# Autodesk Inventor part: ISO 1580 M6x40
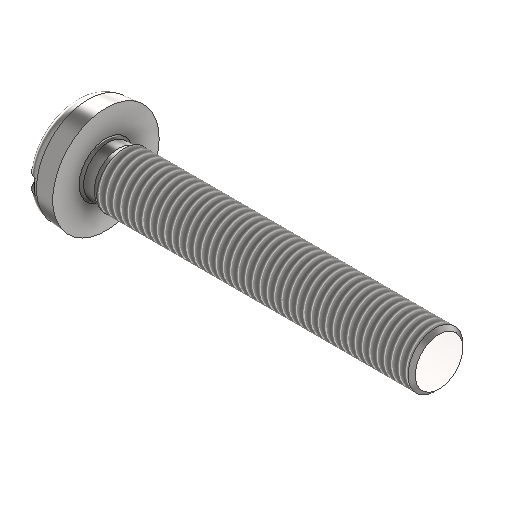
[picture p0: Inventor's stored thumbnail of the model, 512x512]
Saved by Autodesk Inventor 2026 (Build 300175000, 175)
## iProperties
Created: 2015-09
Part Number: ISO 1580 M6x40
Material: Steel, Mild
Document SubType Name: Modeling
Designer: Lars Bertram Pedersen
Mass: 10.5111 g
Surface Area: 10.1633 cm^2
Volume: 1.33899 cm^3
Density: 7.85 g/cm^3
Appearance: Semi-Polished
Description: Slotted pan head screws
Stock Number: Lager
Author: Lars Bertram Pedersen
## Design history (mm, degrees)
sketch "Sketch1"
  geometry: L1 (-3.6, 0)-(36.4, 0); L2 (36.4, 0)-(36.4, 3); L3 (36.4, 3)-(2, 3); L4 (2, 3)-(1.389, 2.689); L5 (1.389, 2.689)-(0, 2.689); L6 (0, 2.689)-(0, 5.815); L7 (-3.6, 0)-(-3.6, 5.5); L8 (0, 5.815)-(-3.6, 5.5); 1 further point
  constraints: 16 end point, 3 parallel, 1 horizontal, 1 perpendicular
  dimensions: "d18" = 36.4 distance between parallel lines of L2 L6; "d19" = 6 diameter of L3 L1; "d20" = 85 deg angle of L7 L8; "d21" = 153 deg angle of L5 L4; "d22" = 5.37716 diameter of L5 L1; "d23" = 11 diameter of L7.end L1
revolve "Revolution1" sketch "Sketch1" stored, may be unused: angle "d24" = 90 deg
chamfer "Chamfer1" distance "d25" = 0.4; stored, may be unused: second distance "d26" = 2, angle "d27" = 45 deg
thread "Thread1" dims "d28" = 10, "d29" = 0
fillet "Fillet1" dims "d34" = 1.8
sketch "Sketch2"
  geometry: L1 (0.8, -7.5)-(-0.8, -7.5); L2 (-0.8, -7.5)-(-0.8, 7.5); L3 (-0.8, 7.5)-(0.8, 7.5); L4 (0.8, 7.5)-(0.8, -7.5); L5 (0.8, -7.5)-(-0.8, 7.5); L6 (-0.8, -7.5)-(0.8, 7.5); 1 further point
  constraints: 12 end point, 2 midpoint, 2 parallel, 1 horizontal, 1 perpendicular
  dimensions: "d30" = 1.6 distance of L2.end L3.end; "d31" = 15 distance of L3.end L1.start
extrude "Extrusion1" cut sketch "Sketch2" distance "d32" = 1.4; taper "d33" = 0 deg
fillet "Fillet2" dims "d35" = 0.25
body "Solid1"
other parameters: "d9" = 38 [user parameter], "d10" = 3.6 [user parameter], "d11" = 6 (= d16) [user parameter], "d12" = 5.3865 [user parameter], "d13" = 12 [user parameter], "d14" = 5 deg [user parameter], "d15" = 0.61345 (= 0.61345 x d17) [user parameter], "d16" = 6 [user parameter; used in 1 equation term], "d17" = 1 [user parameter; used in 1 equation term]
